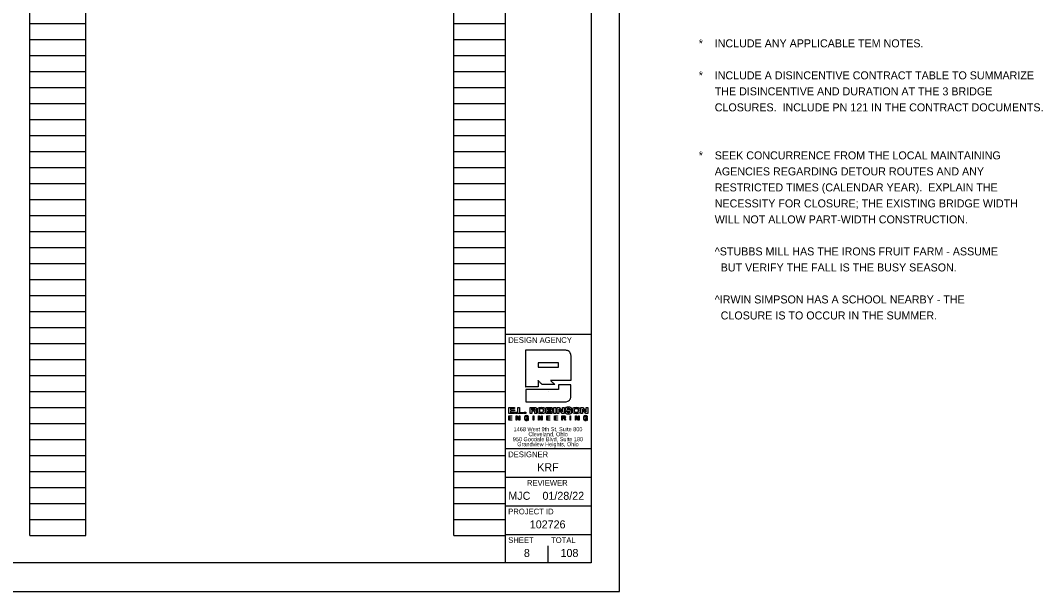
# Model space of a CAD drawing. Extents: x 0 to 41.4, y 0 to 22.
# Drawn here: x 23.52 to 41.4, y 0 to 9.99 of the extents above; entities that cross this region are included whole.
import ezdxf

# ---------------------------------------------------------------- set-up
doc = ezdxf.new("R2010")
doc.units = 0
for name, color, linetype in [('SH_Border', 7, 'Continuous'), ('SH_Cut_Line', 7, 'Continuous'), ('SH_Data', 7, 'Continuous'), ('SH_Text', 7, 'Continuous')]:
    doc.layers.add(name, color=color, linetype=linetype)

msp = doc.modelspace()

# ---------------------------------------------------------------- linework, layer by layer
at = {"layer": 'SH_Border'}
for p, q in [((32, 0.5), (32, 21.5)), ((32, 4.5), (33.5, 4.5)), ((32, 2.5), (33.5, 2.5)), ((32, 2), (33.5, 2)), ((32, 1.5), (33.5, 1.5)), ((32, 1), (33.5, 1))]:
    msp.add_line(p, q, dxfattribs=at)
msp.add_lwpolyline([(1.5, 21.5), (33.5, 21.5), (33.5, 0.5), (1.5, 0.5)], close=True, dxfattribs=at)
at = {"layer": 'SH_Cut_Line'}
msp.add_lwpolyline([(0, 0), (34, 0), (34, 22), (0, 22)], close=True, dxfattribs=at)
at = {"layer": 'SH_Data'}
for p, q in [((23.68, 0.98), (23.68, 21.14)), ((24.66, 0.98), (24.66, 21.14)), ((31.1, 0.98), (31.1, 21.14)), ((32, 0.98), (32, 21.14)), ((23.68, 9.94), (24.66, 9.94)), ((31.1, 9.94), (32, 9.94)), ((23.68, 9.66), (24.66, 9.66)), ((31.1, 9.66), (32, 9.66)), ((23.68, 9.38), (24.66, 9.38)), ((31.1, 9.38), (32, 9.38)), ((23.68, 9.1), (24.66, 9.1)), ((31.1, 9.1), (32, 9.1)), ((23.68, 8.82), (24.66, 8.82)), ((31.1, 8.82), (32, 8.82)), ((23.68, 8.54), (24.66, 8.54)), ((31.1, 8.54), (32, 8.54)), ((23.68, 8.26), (24.66, 8.26)), ((31.1, 8.26), (32, 8.26)), ((23.68, 7.98), (24.66, 7.98)), ((31.1, 7.98), (32, 7.98)), ((23.68, 7.7), (24.66, 7.7)), ((31.1, 7.7), (32, 7.7)), ((23.68, 7.42), (24.66, 7.42)), ((31.1, 7.42), (32, 7.42)), ((23.68, 7.14), (24.66, 7.14)), ((31.1, 7.14), (32, 7.14)), ((23.68, 6.86), (24.66, 6.86)), ((31.1, 6.86), (32, 6.86)), ((23.68, 6.58), (24.66, 6.58)), ((31.1, 6.58), (32, 6.58)), ((23.68, 6.3), (24.66, 6.3)), ((31.1, 6.3), (32, 6.3)), ((23.68, 6.02), (24.66, 6.02)), ((31.1, 6.02), (32, 6.02)), ((23.68, 5.74), (24.66, 5.74)), ((31.1, 5.74), (32, 5.74)), ((23.68, 5.46), (24.66, 5.46)), ((31.1, 5.46), (32, 5.46)), ((23.68, 5.18), (24.66, 5.18)), ((31.1, 5.18), (32, 5.18)), ((23.68, 4.9), (24.66, 4.9)), ((31.1, 4.9), (32, 4.9)), ((23.68, 4.62), (24.66, 4.62)), ((31.1, 4.62), (32, 4.62)), ((23.68, 4.34), (24.66, 4.34)), ((31.1, 4.34), (32, 4.34)), ((23.68, 4.06), (24.66, 4.06)), ((31.1, 4.06), (32, 4.06)), ((32.929, 4.003), (32.574, 4.003)), ((32.574, 4.003), (32.574, 3.925)), ((32.929, 3.925), (32.929, 4.003)), ((23.68, 3.78), (24.66, 3.78)), ((31.1, 3.78), (32, 3.78)), ((32.574, 3.925), (32.929, 3.925)), ((23.68, 3.5), (24.66, 3.5)), ((31.1, 3.5), (32, 3.5)), ((32.75, 3.5), (32.75, 3.5)), ((23.68, 3.22), (24.66, 3.22)), ((31.1, 3.22), (32, 3.22)), ((32.463, 3.201), (32.463, 3.173)), ((32.743, 3.202), (32.743, 3.178)), ((32.743, 3.159), (32.743, 3.133)), ((33.001, 3.066), (33.001, 3.039)), ((23.68, 2.94), (24.66, 2.94)), ((31.1, 2.94), (32, 2.94)), ((33.001, 3.039), (33.023, 3.039)), ((23.68, 2.66), (24.66, 2.66)), ((31.1, 2.66), (32, 2.66)), ((23.68, 2.38), (24.66, 2.38)), ((31.1, 2.38), (32, 2.38)), ((23.68, 2.1), (24.66, 2.1)), ((31.1, 2.1), (32, 2.1)), ((23.68, 1.82), (24.66, 1.82)), ((31.1, 1.82), (32, 1.82)), ((23.68, 1.54), (24.66, 1.54)), ((31.1, 1.54), (32, 1.54)), ((23.68, 1.26), (24.66, 1.26)), ((31.1, 1.26), (32, 1.26)), ((23.68, 0.98), (24.66, 0.98)), ((31.1, 0.98), (32, 0.98)), ((32.75, 0.5), (32.75, 0.8)), ((32.375, 0.675), (32.375, 0.675))]:
    msp.add_line(p, q, dxfattribs=at)
for points in [[(32.06, 3.221), (32.161, 3.221), (32.161, 3.201), (32.089, 3.201), (32.089, 3.178), (32.158, 3.178), (32.158, 3.158), (32.089, 3.158), (32.089, 3.133), (32.162, 3.133), (32.162, 3.113), (32.06, 3.113), (32.06, 3.221)], [(32.22, 3.221), (32.249, 3.221), (32.249, 3.134), (32.316, 3.134), (32.316, 3.113), (32.22, 3.113), (32.22, 3.221)], [(32.851, 3.221), (32.881, 3.221), (32.881, 3.113), (32.851, 3.113), (32.851, 3.221)], [(32.999, 3.221), (33.027, 3.221), (33.027, 3.113), (32.995, 3.113), (32.936, 3.189), (32.936, 3.189), (32.936, 3.113), (32.907, 3.113), (32.907, 3.221), (32.941, 3.221), (32.999, 3.146), (32.999, 3.146), (32.999, 3.221)], [(33.413, 3.221), (33.442, 3.221), (33.442, 3.113), (33.41, 3.113), (33.35, 3.189), (33.35, 3.189), (33.35, 3.113), (33.321, 3.113), (33.321, 3.221), (33.356, 3.221), (33.413, 3.146), (33.413, 3.146), (33.413, 3.221)], [(32.059, 3.075), (32.114, 3.075), (32.114, 3.066), (32.07, 3.066), (32.07, 3.041), (32.111, 3.041), (32.111, 3.032), (32.07, 3.032), (32.07, 3.005), (32.114, 3.005), (32.114, 2.996), (32.059, 2.996), (32.059, 3.075)], [(32.175, 3.139), (32.205, 3.139), (32.205, 3.113), (32.175, 3.113), (32.175, 3.139)], [(32.191, 3.075), (32.203, 3.075), (32.244, 3.011), (32.244, 3.011), (32.244, 3.075), (32.254, 3.075), (32.254, 2.996), (32.243, 2.996), (32.202, 3.059), (32.201, 3.059), (32.201, 2.996), (32.191, 2.996), (32.191, 3.075)], [(32.331, 3.139), (32.361, 3.139), (32.361, 3.113), (32.331, 3.113), (32.331, 3.139)], [(32.487, 3.075), (32.498, 3.075), (32.498, 2.996), (32.487, 2.996), (32.487, 3.075)], [(32.581, 3.075), (32.592, 3.075), (32.633, 3.011), (32.633, 3.011), (32.633, 3.075), (32.643, 3.075), (32.643, 2.996), (32.632, 2.996), (32.591, 3.059), (32.591, 3.059), (32.591, 2.996), (32.581, 2.996), (32.581, 3.075)], [(32.726, 3.075), (32.781, 3.075), (32.781, 3.066), (32.737, 3.066), (32.737, 3.041), (32.778, 3.041), (32.778, 3.032), (32.737, 3.032), (32.737, 3.005), (32.781, 3.005), (32.781, 2.996), (32.726, 2.996), (32.726, 3.075)], [(32.859, 3.075), (32.913, 3.075), (32.913, 3.066), (32.869, 3.066), (32.869, 3.041), (32.91, 3.041), (32.91, 3.032), (32.869, 3.032), (32.869, 3.005), (32.913, 3.005), (32.913, 2.996), (32.859, 2.996), (32.859, 3.075)], [(33.133, 3.075), (33.143, 3.075), (33.143, 2.996), (33.133, 2.996), (33.133, 3.075)], [(33.226, 3.075), (33.237, 3.075), (33.279, 3.011), (33.279, 3.011), (33.279, 3.075), (33.289, 3.075), (33.289, 2.996), (33.277, 2.996), (33.236, 3.059), (33.236, 3.059), (33.236, 2.996), (33.226, 2.996), (33.226, 3.075)]]:
    msp.add_lwpolyline(points, dxfattribs=at)
for points, degree in [([(32.356, 3.583), (32.356, 3.586), (32.356, 4.224), (32.356, 4.227)], 2), ([(32.356, 4.227), (32.36, 4.227), (33.03, 4.227), (33.034, 4.227), (33.096, 4.227), (33.147, 4.177), (33.147, 4.114)], 3), ([(33.147, 4.114), (33.147, 4.112), (33.147, 3.694), (33.147, 3.692)], 2), ([(32.929, 3.615), (32.929, 3.615), (33.147, 3.615), (33.147, 3.615), (33.147, 3.615), (33.147, 3.433), (33.147, 3.433), (33.147, 3.37), (33.096, 3.32), (33.034, 3.32), (33.034, 3.32), (32.356, 3.32), (32.356, 3.32), (32.356, 3.32), (32.356, 3.537), (32.356, 3.537), (32.356, 3.537), (32.929, 3.537), (32.929, 3.537), (32.929, 3.537), (32.929, 3.615), (32.929, 3.615)], 3), ([(32.574, 3.583), (32.573, 3.583), (32.357, 3.583), (32.356, 3.583)], 2), ([(32.645, 3.621), (32.645, 3.621), (32.574, 3.691), (32.574, 3.692)], 2), ([(32.574, 3.692), (32.574, 3.691), (32.574, 3.583), (32.574, 3.583)], 2), ([(32.866, 3.621), (32.865, 3.621), (32.646, 3.621), (32.645, 3.621)], 2), ([(33.147, 3.692), (33.145, 3.692), (32.795, 3.692), (32.793, 3.692)], 2), ([(32.793, 3.692), (32.793, 3.691), (32.866, 3.621), (32.866, 3.621)], 2), ([(32.433, 3.113), (32.433, 3.113), (32.433, 3.221), (32.433, 3.221)], 2), ([(32.433, 3.221), (32.433, 3.221), (32.512, 3.221), (32.512, 3.221), (32.542, 3.221), (32.545, 3.203), (32.546, 3.192)], 3), ([(32.631, 3.11), (32.573, 3.11), (32.567, 3.145), (32.565, 3.167), (32.564, 3.19), (32.573, 3.224), (32.631, 3.224)], 3), ([(32.631, 3.224), (32.69, 3.224), (32.695, 3.189), (32.697, 3.167), (32.699, 3.144), (32.69, 3.11), (32.631, 3.11)], 3), ([(32.714, 3.113), (32.714, 3.113), (32.714, 3.221), (32.714, 3.221)], 2), ([(32.714, 3.221), (32.714, 3.221), (32.795, 3.221), (32.795, 3.221)], 2), ([(32.795, 3.221), (32.81, 3.218), (32.826, 3.214), (32.826, 3.194)], 2), ([(33.126, 3.19), (33.124, 3.204), (33.111, 3.206), (33.099, 3.206), (33.087, 3.206), (33.079, 3.2), (33.079, 3.193), (33.079, 3.187), (33.084, 3.184), (33.091, 3.183), (33.091, 3.183), (33.128, 3.177), (33.128, 3.177), (33.148, 3.173), (33.163, 3.166), (33.163, 3.146), (33.163, 3.126), (33.149, 3.11), (33.107, 3.11), (33.08, 3.11), (33.046, 3.113), (33.045, 3.147), (33.045, 3.147), (33.079, 3.147), (33.079, 3.147), (33.079, 3.132), (33.094, 3.129), (33.107, 3.129), (33.121, 3.129), (33.13, 3.134), (33.13, 3.143), (33.13, 3.151), (33.123, 3.154), (33.112, 3.155), (33.112, 3.155), (33.085, 3.16), (33.085, 3.16), (33.066, 3.162), (33.047, 3.168), (33.047, 3.19), (33.047, 3.215), (33.067, 3.224), (33.101, 3.224), (33.124, 3.224), (33.157, 3.221), (33.159, 3.19), (33.159, 3.19), (33.126, 3.19), (33.126, 3.19)], 3), ([(33.242, 3.11), (33.183, 3.11), (33.178, 3.145), (33.176, 3.167), (33.174, 3.19), (33.183, 3.224), (33.242, 3.224)], 3), ([(33.242, 3.224), (33.3, 3.224), (33.306, 3.189), (33.308, 3.167), (33.309, 3.144), (33.3, 3.11), (33.242, 3.11)], 3), ([(32.396, 3.006), (32.39, 2.998), (32.38, 2.994), (32.37, 2.994), (32.347, 2.994), (32.333, 3.014), (32.333, 3.034), (32.333, 3.057), (32.346, 3.077), (32.37, 3.077), (32.388, 3.077), (32.401, 3.069), (32.404, 3.051), (32.404, 3.051), (32.394, 3.051), (32.394, 3.051), (32.392, 3.062), (32.382, 3.068), (32.37, 3.068), (32.351, 3.068), (32.344, 3.051), (32.344, 3.034), (32.344, 3.018), (32.353, 3.003), (32.37, 3.003), (32.387, 3.003), (32.396, 3.015), (32.396, 3.029), (32.396, 3.029), (32.371, 3.029), (32.371, 3.029), (32.371, 3.029), (32.371, 3.038), (32.371, 3.038), (32.371, 3.038), (32.405, 3.038), (32.405, 3.038), (32.405, 3.038), (32.405, 2.996), (32.405, 2.996), (32.405, 2.996), (32.398, 2.996), (32.398, 2.996), (32.398, 2.996), (32.396, 3.006), (32.396, 3.006)], 3), ([(32.463, 3.113), (32.462, 3.113), (32.433, 3.113), (32.433, 3.113)], 2), ([(32.499, 3.153), (32.499, 3.153), (32.463, 3.153), (32.463, 3.153)], 2), ([(32.463, 3.173), (32.463, 3.173), (32.502, 3.173), (32.502, 3.173), (32.508, 3.173), (32.516, 3.177), (32.516, 3.187), (32.516, 3.198), (32.507, 3.201), (32.5, 3.201), (32.5, 3.201), (32.463, 3.201), (32.463, 3.201), (32.463, 3.201), (32.463, 3.173), (32.463, 3.173)], 3), ([(32.463, 3.173), (32.476, 3.173), (32.489, 3.173), (32.508, 3.173), (32.516, 3.177), (32.516, 3.198), (32.507, 3.201), (32.488, 3.201), (32.475, 3.201), (32.463, 3.201)], 3), ([(32.463, 3.153), (32.463, 3.152), (32.463, 3.113), (32.463, 3.113)], 2), ([(32.518, 3.113), (32.516, 3.118), (32.516, 3.122), (32.516, 3.134), (32.515, 3.149), (32.508, 3.15), (32.499, 3.153)], 3), ([(32.55, 3.113), (32.55, 3.113), (32.518, 3.113), (32.518, 3.113)], 2), ([(32.546, 3.192), (32.544, 3.179), (32.542, 3.17), (32.53, 3.166)], 2), ([(32.53, 3.166), (32.53, 3.166), (32.53, 3.165), (32.53, 3.165)], 2), ([(32.53, 3.165), (32.543, 3.163), (32.544, 3.147), (32.544, 3.136)], 2), ([(32.544, 3.136), (32.544, 3.131), (32.548, 3.119), (32.55, 3.113)], 2), ([(32.631, 3.13), (32.658, 3.13), (32.667, 3.15), (32.667, 3.167), (32.667, 3.184), (32.658, 3.204), (32.631, 3.204), (32.604, 3.204), (32.595, 3.184), (32.595, 3.167), (32.595, 3.15), (32.604, 3.13), (32.631, 3.13)], 3), ([(32.631, 3.204), (32.604, 3.204), (32.595, 3.184), (32.595, 3.167), (32.595, 3.15), (32.604, 3.13), (32.631, 3.13)], 3), ([(32.631, 3.13), (32.658, 3.13), (32.667, 3.15), (32.667, 3.167), (32.667, 3.184), (32.658, 3.204), (32.631, 3.204)], 3), ([(32.829, 3.145), (32.827, 3.132), (32.824, 3.113), (32.791, 3.113), (32.791, 3.113), (32.714, 3.113), (32.714, 3.113)], 3), ([(32.743, 3.178), (32.743, 3.178), (32.784, 3.178), (32.784, 3.178), (32.791, 3.178), (32.796, 3.182), (32.796, 3.19), (32.796, 3.197), (32.793, 3.202), (32.78, 3.202), (32.78, 3.202), (32.743, 3.202), (32.743, 3.202), (32.743, 3.202), (32.743, 3.178), (32.743, 3.178)], 3), ([(32.743, 3.178), (32.757, 3.178), (32.771, 3.178), (32.791, 3.181), (32.791, 3.183), (32.792, 3.197), (32.793, 3.202), (32.768, 3.202), (32.756, 3.202), (32.743, 3.202)], 3), ([(32.743, 3.133), (32.743, 3.133), (32.787, 3.133), (32.787, 3.133), (32.796, 3.133), (32.8, 3.139), (32.8, 3.146), (32.8, 3.155), (32.794, 3.159), (32.784, 3.159), (32.784, 3.159), (32.743, 3.159), (32.743, 3.159), (32.743, 3.159), (32.743, 3.133), (32.743, 3.133)], 3), ([(32.743, 3.133), (32.758, 3.133), (32.772, 3.133), (32.796, 3.133), (32.8, 3.139), (32.8, 3.155), (32.794, 3.159), (32.77, 3.159), (32.757, 3.159), (32.743, 3.159)], 3), ([(32.826, 3.194), (32.824, 3.186), (32.822, 3.175), (32.812, 3.172)], 2), ([(32.812, 3.172), (32.812, 3.172), (32.812, 3.172), (32.812, 3.172)], 2), ([(32.812, 3.172), (32.824, 3.17), (32.827, 3.156), (32.829, 3.145)], 2), ([(32.991, 3.075), (32.991, 3.075), (33.027, 3.075), (33.028, 3.075), (33.042, 3.075), (33.051, 3.067), (33.051, 3.054)], 3), ([(32.991, 2.996), (32.991, 2.997), (32.991, 3.074), (32.991, 3.075)], 2), ([(33.023, 3.039), (33.033, 3.039), (33.041, 3.041), (33.041, 3.052), (33.041, 3.06), (33.037, 3.066), (33.027, 3.066), (33.027, 3.066), (33.001, 3.066), (33.001, 3.066), (33.001, 3.066), (33.001, 3.039), (33.001, 3.039), (33.001, 3.039), (33.023, 3.039), (33.023, 3.039)], 3), ([(33.023, 3.039), (33.033, 3.039), (33.041, 3.041), (33.041, 3.06), (33.037, 3.066), (33.018, 3.066), (33.01, 3.066), (33.001, 3.066)], 3), ([(33.051, 3.054), (33.049, 3.045), (33.047, 3.037), (33.038, 3.034)], 2), ([(33.242, 3.13), (33.269, 3.13), (33.278, 3.15), (33.278, 3.167), (33.278, 3.184), (33.269, 3.204), (33.242, 3.204), (33.215, 3.204), (33.205, 3.184), (33.205, 3.167), (33.205, 3.15), (33.215, 3.13), (33.242, 3.13)], 3), ([(33.242, 3.204), (33.215, 3.204), (33.205, 3.184), (33.205, 3.167), (33.205, 3.15), (33.215, 3.13), (33.242, 3.13)], 3), ([(33.242, 3.13), (33.269, 3.13), (33.278, 3.15), (33.278, 3.167), (33.278, 3.184), (33.269, 3.204), (33.242, 3.204)], 3), ([(33.43, 3.006), (33.424, 2.998), (33.414, 2.994), (33.405, 2.994), (33.382, 2.994), (33.368, 3.014), (33.368, 3.034), (33.368, 3.057), (33.38, 3.077), (33.405, 3.077), (33.422, 3.077), (33.436, 3.069), (33.439, 3.051), (33.439, 3.051), (33.429, 3.051), (33.429, 3.051), (33.426, 3.062), (33.417, 3.068), (33.405, 3.068), (33.386, 3.068), (33.378, 3.051), (33.378, 3.034), (33.378, 3.018), (33.388, 3.003), (33.405, 3.003), (33.421, 3.003), (33.431, 3.015), (33.43, 3.029), (33.43, 3.029), (33.405, 3.029), (33.405, 3.029), (33.405, 3.029), (33.405, 3.038), (33.405, 3.038), (33.405, 3.038), (33.44, 3.038), (33.44, 3.038), (33.44, 3.038), (33.44, 2.996), (33.44, 2.996), (33.44, 2.996), (33.433, 2.996), (33.433, 2.996), (33.433, 2.996), (33.43, 3.006), (33.43, 3.006)], 3), ([(33.001, 2.996), (33.001, 2.996), (32.991, 2.996), (32.991, 2.996)], 2), ([(33.04, 3.016), (33.038, 3.023), (33.037, 3.03), (33.027, 3.03), (33.027, 3.03), (33.001, 3.03), (33.001, 3.03)], 3), ([(33.001, 3.03), (33.001, 3.03), (33.001, 2.996), (33.001, 2.996)], 2), ([(33.038, 3.034), (33.038, 3.034), (33.038, 3.034), (33.038, 3.034)], 2), ([(33.038, 3.034), (33.044, 3.029), (33.047, 3.025), (33.048, 3.018)], 2), ([(33.043, 2.996), (33.042, 3), (33.041, 3.008), (33.04, 3.016)], 2), ([(33.054, 2.996), (33.054, 2.996), (33.043, 2.996), (33.043, 2.996)], 2), ([(33.048, 3.018), (33.049, 3.01), (33.052, 3.002), (33.054, 2.996)], 2)]:
    msp.add_open_spline(points, degree=degree, dxfattribs=at)

# ---------------------------------------------------------------- texts
for s, height, p in [('DESIGN AGENCY', 0.1, (32.05, 4.35)), ('1468 West 9th St, Suite 800', 0.07, (32.145, 2.805)), ('950 Goodale Blvd, Suite 180', 0.07, (32.13, 2.63)), ('Cleveland, Ohio', 0.07, (32.404, 2.717)), ('Grandview Heights, Ohio', 0.07, (32.208, 2.542)), ('DESIGNER', 0.1, (32.05, 2.35)), ('KRF', 0.14, (32.559, 2.105)), ('REVIEWER', 0.1, (32.378, 1.85)), ('MJC', 0.14, (32.053, 1.605)), ('01/28/22', 0.14, (32.65, 1.605)), ('PROJECT ID', 0.1, (32.05, 1.35)), ('102726', 0.14, (32.428, 1.105)), ('SHEET', 0.1, (32.05, 0.85)), ('TOTAL', 0.1, (32.8, 0.85)), ('8', 0.14, (32.325, 0.605)), ('108', 0.14, (32.966, 0.605))]:
    msp.add_text(s, height=height, dxfattribs=at).set_placement(p)
at = {"layer": 'SH_Text'}
for s, p in [('*', (35.384, 9.52)), ('INCLUDE ANY APPLICABLE TEM NOTES. ', (35.664, 9.52)), ('*', (35.384, 8.96)), ('INCLUDE A DISINCENTIVE CONTRACT TABLE TO SUMMARIZE ', (35.664, 8.96)), ('THE DISINCENTIVE AND DURATION AT THE 3 BRIDGE ', (35.664, 8.68)), ('CLOSURES.  INCLUDE PN 121 IN THE CONTRACT DOCUMENTS.', (35.664, 8.4)), ('*', (35.384, 7.56)), ('SEEK CONCURRENCE FROM THE LOCAL MAINTAINING ', (35.664, 7.56)), ('AGENCIES REGARDING DETOUR ROUTES AND ANY ', (35.664, 7.28)), ('RESTRICTED TIMES (CALENDAR YEAR).\xa0 EXPLAIN THE ', (35.664, 7)), ('NECESSITY FOR CLOSURE; THE EXISTING BRIDGE WIDTH ', (35.664, 6.72)), ('WILL NOT ALLOW PART-WIDTH CONSTRUCTION. ', (35.664, 6.44)), ('^ STUBBS MILL HAS THE IRONS FRUIT FARM - ASSUME ', (35.664, 5.88)), ('  BUT VERIFY THE FALL IS THE BUSY SEASON.', (35.664, 5.6)), ('^ IRWIN SIMPSON HAS A SCHOOL NEARBY - THE ', (35.664, 5.04)), ('  CLOSURE IS TO OCCUR IN THE SUMMER.', (35.664, 4.76))]:
    msp.add_text(s, height=0.14, dxfattribs=at).set_placement(p)

doc.saveas('drawing.dxf')
